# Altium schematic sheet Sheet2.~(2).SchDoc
size A4
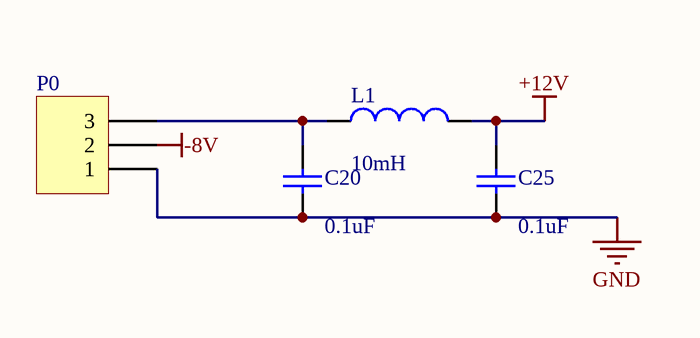
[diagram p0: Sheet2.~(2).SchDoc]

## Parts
C20  value 0.1uF  [RAD-0.3]  (hidden comment: Cap)
C25  value 0.1uF  [RAD-0.3]  (hidden comment: Cap)
L1  value 10mH  [0402-A]  (hidden comment: Inductor)
P0  Header 3  [HDR1X3]  (value not drawn)

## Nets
+12V: C25.2 L1.2
-8V: P0.2
GND: C20.1 C25.1 P0.1
NetC20_2: C20.2 L1.1 P0.3

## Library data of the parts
C20 C25 = Cap: Capacitor
L1 = Inductor: Code_IEC: 1005
P0 = Header 3: Header, 3-Pin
